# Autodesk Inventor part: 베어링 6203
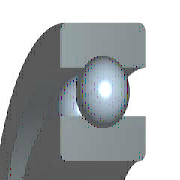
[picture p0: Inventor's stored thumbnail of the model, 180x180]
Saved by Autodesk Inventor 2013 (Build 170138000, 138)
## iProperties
IsCustomPart: 1
Created: 2012-02
Part Number: 베어링 6203
Material: 강철, 연강
Description: 깊은 그루브 볼 베어링
Document SubType Name: Modeling
Standard: KS B 2023
Designer: mduedu
Standards Organization: KS
Language: ko-KR
Size Designation: 6203 - 17 x 40 x 12
Categories: <MemberInstance><Categories><Category DisplayName="샤프트 부품" InternalName="7f7aeb1f-a693-4053-b835-cee3144e0d98" Mnemonic="SHFT"><Category DisplayName="베어링" Inter
Density: 1 g/cm^3
Author: mduedu
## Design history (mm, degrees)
sketch "스케치" dims "d0" = 5.98 (= -0.26 x WD + 0.26 x BD)
  geometry: L1 (3.01, 14.25)-(8.99, 14.25); L2 (6, 14.25)-(6, 11.26); L3 (6, 14.25)-(6, 17.24); L4 (3.778, 12.249)-(0, 12.249); L5 (0, 8.5)-(12, 8.5); L6 (3.778, 16.251)-(0, 16.251); L7 (0, 20)-(12, 20); L8 (12, 8.5)-(12, 12.249); L9 (8.222, 12.249)-(12, 12.249); L10 (8.222, 16.251)-(12, 16.251); L11 (12, 20)-(12, 16.251); L12 (-1.4, 0)-(8.4, 0) reference; L13 (0, -0.3)-(0, 5.3) reference
  constraints: 22 end point, 4 point on line, 2 collinear, 2 perpendicular, 2 symmetric about line, 1 midpoint, 1 parallel, 14 other
  dimensions: "d9" = 17 diameter of L5 L12 (= WD); "d11" = 40 diameter of L7 L12 (= BD); "d12" = 12 distance between parallel lines of L8 L13 (= KB); "d13" = 24.498 diameter of L9 L12 (= 0.326 x BD + 0.674 x WD)
revolve "본체" stored, may be unused: angle "d6" = 90 deg
revolve "볼" stored, may be unused: angle "d7" = 90 deg
pattern_circular "IDS_ARRAYBALL[SIMPL:T]" dims angle "d3" = 360 deg
body "Solid1"
fillet "모깎기1" dims "d1" = 0.6 (= KRS)
other parameters: "WD" = 17 [user parameter; used in 5 equation terms], "BD" = 40 [user parameter; used in 5 equation terms], "KB" = 12 [user parameter; used in 1 equation term], "KRS" = 0.6 [user parameter; used in 1 equation term], "d4" = 0, "d5" = 0, "d8" = 0, "d14" = 0, "d15" = 0, "BBA" = 0 [user parameter], "BC0" = 4750000 [user parameter], "BC" = 9560000 [user parameter], "WR" = 8.5 (= 0.5 x WD) [user parameter]
